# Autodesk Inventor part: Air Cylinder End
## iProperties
Created: 2010-01
Part Number: Air Cylinder End
Document SubType Name: Modeling
Designer: cmcfadden
Density: 1 g/cm^3
Author: cmcfadden
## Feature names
1. Extrusion1
2. Chamfer1
3. Extrusion2
4. Extrusion3
